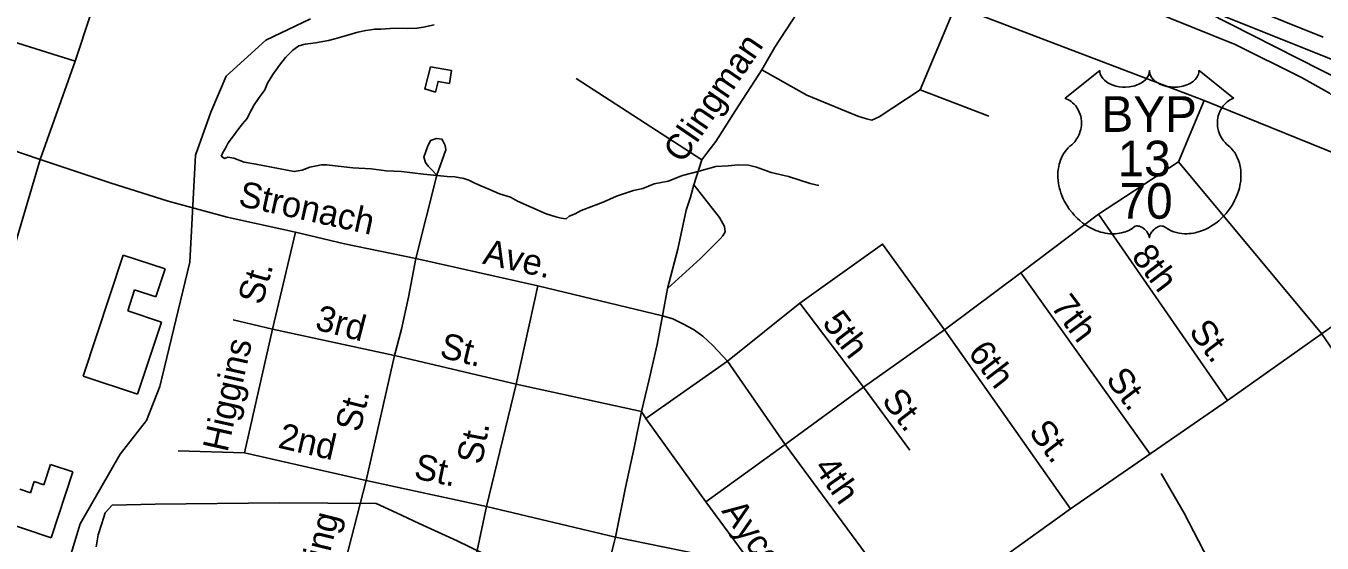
# Model space of a CAD drawing. Extents: x 2260773 to 2342389, y 552869 to 618546.
# Drawn here: x 2301642 to 2306454, y 599328 to 601248 of the extents above; entities that cross this region are included whole.
import ezdxf

# ---------------------------------------------------------------- set-up
doc = ezdxf.new("R2010")
doc.units = 0
for name, color, linetype in [('Exist Cultural Warehouse Building Footprint', 7, 'Continuous'), ('Exist Hydrographic Misc Water Feature', 7, 'Continuous'), ('Exist Road Non-System Type 51', 7, 'Continuous'), ('Exist Road Non-System Type 51 Label', 7, 'Continuous'), ('Exist Road Primary Interstate Ramp 1 Lane Attributed', 7, 'Continuous'), ('Exist Road Primary US Divided Attributed', 7, 'Continuous'), ('Exist Road Primary US Service Attributed', 7, 'Continuous'), ('Exist Road Primary US Shield CELL', 7, 'Continuous'), ('Exist Road Primary US Shield Number Label', 7, 'Continuous'), ('Exist Road Primary US UnDivided 4 Lane Attributed', 7, 'Continuous'), ('Exist Road Secondary Type 51 Undivided 4 Lane Attributed', 7, 'Continuous')]:
    doc.layers.add(name, color=color, linetype=linetype)

msp = doc.modelspace()

# ---------------------------------------------------------------- linework, layer by layer
at = {"layer": 'Exist Cultural Warehouse Building Footprint'}
for p, q in [((2302003.2, 600397.2), (2301854.2, 599947.3)), ((2302158.7, 600345.7), (2302003.2, 600397.2)), ((2302124.4, 600241.9), (2302158.7, 600345.7)), ((2302019.7, 600189.9), (2302045.5, 600268)), ((2302045.5, 600268), (2302124.4, 600241.9)), ((2302145.1, 600148.4), (2302019.7, 600189.9)), ((2302056.4, 599880.4), (2302145.1, 600148.4)), ((2301854.2, 599947.3), (2302056.4, 599880.4)), ((2301708.1, 599544.3), (2301733.2, 599619.6)), ((2301733.2, 599619.6), (2301816.7, 599591.8)), ((2301816.7, 599591.8), (2301735.4, 599347.4)), ((2301658.7, 599514.7), (2301672.5, 599556.1)), ((2301672.5, 599556.1), (2301708.1, 599544.3)), ((2301619.8, 599527.7), (2301658.7, 599514.7)), ((2301735.4, 599347.4), (2301497.8, 599426.6))]:
    msp.add_line(p, q, dxfattribs=at)
at = {"layer": 'Exist Hydrographic Misc Water Feature'}
for points in [[(2301559.9, 596453.9), (2301656.9, 596697.4), (2301736.1, 597048.4), (2301737.9, 597655.5), (2301785.1, 597906.8), (2301769.9, 598556), (2301742, 598889.5), (2301774, 598972.8), (2301772, 599163.1), (2301843.9, 599399), (2301992, 599657.6), (2302090, 599783), (2302139, 599909.7), (2302249.9, 600370.4), (2302271.1, 600768.2), (2302328.1, 600928), (2302385.1, 601061.6), (2302532.9, 601195.6), (2302699, 601274.5)], [(2303157.9, 601252.1), (2303117.9, 601244), (2303093.7, 601239.5), (2303058.1, 601239.2), (2303016.2, 601240.6), (2302994.1, 601238.7), (2302960, 601236.1), (2302935.8, 601236.1), (2302922.3, 601233.7), (2302904.1, 601231.6), (2302874.1, 601225.1), (2302832.5, 601212.7), (2302788.4, 601200.3), (2302764.8, 601194.2), (2302716.6, 601185.5), (2302698.8, 601183.4), (2302678.5, 601181.2), (2302654.9, 601175), (2302633.2, 601158.8), (2302605.5, 601130.5), (2302583.8, 601102.2), (2302558.1, 601067.9), (2302538.3, 601035.6), (2302528.8, 601011.5), (2302505.2, 600979.4), (2302489.7, 600955.3), (2302472, 600923.1), (2302463.8, 600904.9), (2302446, 600884.8), (2302428.3, 600862.8), (2302412.8, 600840.4), (2302393.1, 600814.1), (2302381.4, 600792), (2302373, 600778.3), (2302369.7, 600768.2), (2302367.2, 600764.1)], [(2303143.4, 601096.2), (2303221.5, 601083.2), (2303213.9, 601034.9), (2303171.9, 601042.4), (2303162.2, 601002.5), (2303122.4, 601014.2), (2303143.4, 601096.2)], [(2304585.3, 600656), (2304553.5, 600663.6), (2304473.1, 600688.7), (2304408.9, 600704.1), (2304354.8, 600723.6), (2304324.9, 600730.9), (2304286.5, 600732.6), (2304248.8, 600728.2), (2304202.9, 600725.8), (2304141.1, 600709.1), (2304079.2, 600692.5), (2304025.7, 600671.7), (2303973.8, 600661.3), (2303932, 600644.9), (2303897.7, 600636.7), (2303872.1, 600628.4), (2303834, 600615.9), (2303784.4, 600593.3), (2303748.7, 600580.8), (2303703.2, 600562.5), (2303681.2, 600550.4), (2303659.3, 600542), (2303647.6, 600532), (2303629.5, 600533.9), (2303609.2, 600539.4), (2303572.9, 600551), (2303466.7, 600598.1), (2303440.7, 600611.8), (2303400.3, 600625.2), (2303360.3, 600642.6), (2303330.4, 600654.4), (2303306, 600666.1), (2303286.1, 600676), (2303267.8, 600681.6), (2303234, 600687.6), (2303205.7, 600689), (2303117.5, 600698.2), (2303035.7, 600707.3), (2302979.7, 600710.8), (2302923.5, 600718.1), (2302855.7, 600721.4), (2302789.8, 600728.5), (2302759.3, 600732.2), (2302739.8, 600732), (2302695.9, 600723.6), (2302667.8, 600713.2), (2302637.9, 600707.2), (2302612.1, 600712.6), (2302554, 600724.2), (2302496, 600735.4), (2302451.7, 600742.9), (2302413.8, 600756.7), (2302391.4, 600760.5), (2302379.5, 600756.2), (2302367.2, 600764.1)], [(2305856.6, 599586.2), (2305941.7, 599439.2), (2306031.5, 599266.3), (2305926.9, 599163.2), (2305800, 599042)], [(2301961.6, 599468.3), (2301936.2, 599440.1), (2301924.3, 599400), (2301910.6, 599358), (2301903.2, 599314)], [(2303383.1, 599268), (2303242.4, 599336.3), (2303101.7, 599400.8), (2303017.5, 599439.9), (2302942.8, 599475), (2302583.2, 599476.9), (2302121.8, 599472.2), (2301961.6, 599468.3)]]:
    msp.add_lwpolyline(points, dxfattribs=at)
at = {"layer": 'Exist Road Non-System Type 51'}
for p, q in [((2305093.3, 601322.4), (2304962.3, 601010.4)), ((2306016.8, 600971.8), (2305093.3, 601322.4)), ((2301549.4, 601204.5), (2301824.6, 601116.9)), ((2304151.8, 600751.4), (2303684.3, 601053.7)), ((2304962.3, 601010.4), (2305217.3, 600912.8)), ((2305920.8, 600743.5), (2306016.8, 600971.8)), ((2306016.8, 600971.8), (2306596, 600735.6)), ((2301354.4, 600866.2), (2301691.7, 600753.2)), ((2301691.7, 600753.2), (2301694.9, 600752.1)), ((2304151.8, 600751.4), (2304121.9, 600658.4)), ((2305623.4, 600549.8), (2305920.8, 600743.5)), ((2306451.7, 600105.6), (2305920.8, 600743.5)), ((2303089.4, 600384.4), (2303167.6, 600693.8)), ((2305335.3, 600330.9), (2305623.4, 600549.8)), ((2305623.4, 600549.8), (2306103.4, 599857.6)), ((2302642.4, 600482.1), (2302557.4, 600122.2)), ((2303542.7, 600283.2), (2303089.4, 600384.4)), ((2305052, 600119.8), (2305335.3, 600330.9)), ((2305335.3, 600330.9), (2305815.4, 599658.4)), ((2303462.4, 599917.8), (2303542.7, 600283.2)), ((2304005.4, 600171.4), (2303542.7, 600283.2)), ((2304005.4, 600171.4), (2304023.8, 600273.3)), ((2304515.3, 600219), (2304246.2, 600003.3)), ((2304751.4, 599907.2), (2304515.3, 600219)), ((2302557.4, 600122.2), (2302411, 600156.8)), ((2302557.4, 600122.2), (2302453.5, 599662.3)), ((2303010.7, 600023.8), (2302557.4, 600122.2)), ((2305052, 600119.8), (2304751.4, 599907.2)), ((2305519.5, 599454.4), (2305052, 600119.8)), ((2306657.9, 599804.5), (2306451.7, 600105.6)), ((2302905.2, 599560), (2303010.7, 600023.8)), ((2303462.4, 599917.8), (2303010.7, 600023.8)), ((2303943.6, 599790.4), (2304246.2, 600003.3)), ((2304246.2, 600003.3), (2304460.2, 599693.4)), ((2303351.4, 599463.5), (2303462.4, 599917.8)), ((2303926.7, 599816.5), (2303462.4, 599917.8)), ((2304460.2, 599693.4), (2304751.4, 599907.2)), ((2304751.4, 599907.2), (2304923, 599672.6)), ((2303926.7, 599816.5), (2303943.6, 599790.4)), ((2303943.6, 599790.4), (2304165.9, 599480.8)), ((2304460.2, 599693.4), (2304165.9, 599480.8)), ((2304460.2, 599693.4), (2304943.4, 599040.2)), ((2302453.5, 599662.3), (2302207.2, 599670)), ((2302453.5, 599662.3), (2302905.2, 599560)), ((2302905.2, 599560), (2302719.8, 598839.3)), ((2302905.2, 599560), (2303351.4, 599463.5)), ((2303351.4, 599463.5), (2303277.1, 599111.2)), ((2303830.7, 599350.1), (2303351.4, 599463.5)), ((2304165.9, 599480.8), (2304339.1, 599246.2)), ((2303830.7, 599350.1), (2303743.3, 599002.8)), ((2303830.7, 599350.1), (2304315.5, 599251))]:
    msp.add_line(p, q, dxfattribs=at)
for points in [[(2304374.2, 601085.1), (2304421.9, 601169), (2304567.7, 601392.4), (2304681.1, 601608.7), (2304739.4, 601747.6)], [(2304374.2, 601085.1), (2304276.5, 600933.7), (2304203.8, 600818.9), (2304173.8, 600781.3), (2304151.8, 600751.4)], [(2304962.3, 601010.4), (2304809.6, 600911.2), (2304782.9, 600898.6), (2304762.4, 600903.3), (2304731, 600912.8), (2304540.5, 600991.5), (2304374.2, 601085.1)], [(2303167.6, 600693.8), (2303200.6, 600788.1), (2303198.5, 600804), (2303190.2, 600821.9), (2303186.2, 600827.9), (2303166.1, 600829.7), (2303144.3, 600823.4), (2303132.5, 600799.4), (2303118.9, 600761.2), (2303125.3, 600741.2), (2303135.2, 600727.4), (2303147.5, 600715.5), (2303167.6, 600693.8)], [(2302642.4, 600482.1), (2302389, 600538.7), (2302170.2, 600597), (2301954.6, 600665.5), (2301694.9, 600752.1)], [(2304023.8, 600273.3), (2304146.5, 600384.5), (2304219.6, 600457.3), (2304229.5, 600469.3), (2304237.4, 600483.4), (2304235.2, 600503.3), (2304216.8, 600537.2), (2304121.9, 600658.4)], [(2304121.9, 600658.4), (2304109.3, 600612.8), (2304093.5, 600563.9), (2304062, 600419.1), (2304023.8, 600273.3)], [(2303089.4, 600384.4), (2302825, 600439.5), (2302642.4, 600482.1)], [(2304515.3, 600219), (2304822.2, 600438), (2305052, 600119.8)], [(2303010.7, 600023.8), (2303035.9, 600122.7), (2303062.5, 600241), (2303089.4, 600384.4)], [(2304005.4, 600171.4), (2303986, 600064.9), (2303955, 599930.4), (2303926.7, 599816.5)], [(2304005.4, 600171.4), (2304043.2, 600160.8), (2304080.9, 600141.9), (2304120.3, 600121.4), (2304154.9, 600096.2), (2304192.7, 600061.6), (2304246.2, 600003.3)], [(2303926.7, 599816.5), (2303901.5, 599687.1), (2303868.5, 599534.4), (2303830.7, 599350.1)]]:
    msp.add_lwpolyline(points, dxfattribs=at)
at = {"layer": 'Exist Road Primary Interstate Ramp 1 Lane Attributed'}
msp.add_lwpolyline([(2305943.3, 601341.9), (2306533.5, 601042), (2306661.7, 600978.3), (2306830.2, 600877.6), (2306989.1, 600749.3), (2307091.9, 600635.8), (2307128, 600582.8)], dxfattribs=at)
at = {"layer": 'Exist Road Primary US Divided Attributed'}
for points in [[(2306457.9, 601206.3), (2305432, 601620.2), (2304253, 602092.7), (2304041, 602171.5), (2303732.6, 602271.1), (2303680.3, 602281)], [(2305943.3, 601341.9), (2305984.3, 601326.3), (2307418.8, 600752.8)]]:
    msp.add_lwpolyline(points, dxfattribs=at)
at = {"layer": 'Exist Road Primary US Service Attributed'}
msp.add_lwpolyline([(2306887.2, 600412.8), (2306747.5, 600679.3), (2306680.8, 600793.8), (2306629.1, 600867.9), (2306481.5, 600998.5), (2306377.7, 601056.8), (2306131.8, 601179.8), (2304126.9, 601988.9), (2303905.9, 602071.4), (2303809, 602103.4), (2303599.2, 602158.5), (2303401, 602197.7), (2303254.8, 602203.1), (2303190.1, 602190.3), (2302912.5, 602066.8), (2302872.2, 602053), (2302841.5, 602052), (2302810.8, 602061.5), (2302785.3, 602079.5), (2302761, 602109.2)], dxfattribs=at)
at = {"layer": 'Exist Road Primary US Shield CELL'}
msp.add_lwpolyline([(2305629, 601082.2), (2305629.4, 601076.9), (2305630.7, 601070.6), (2305631.6, 601067.3), (2305634.6, 601061.1), (2305639.5, 601053.7), (2305646.3, 601046.5), (2305653.9, 601040.2), (2305659.1, 601036.8), (2305667.9, 601032.1), (2305677.8, 601027.9), (2305688.9, 601024.8), (2305700.2, 601022.5), (2305712.6, 601021.1), (2305724.8, 601020.9), (2305738, 601021.9), (2305752.6, 601024.7), (2305759.4, 601026.4), (2305766.9, 601029), (2305773.9, 601031.9), (2305781.6, 601036), (2305787.7, 601040), (2305792.5, 601043.5), (2305799.4, 601050), (2305804.8, 601056.7), (2305807.1, 601060.5), (2305809.1, 601064.2), (2305811.7, 601071.9), (2305812.5, 601075.4), (2305813, 601082.5), (2305813.5, 601076.5), (2305814.1, 601072.8), (2305815.1, 601069.1), (2305816.6, 601065.3), (2305819.3, 601059.8), (2305822.4, 601055.2), (2305828.1, 601048.5), (2305831.7, 601045.1), (2305835, 601042.5), (2305843.7, 601036.5), (2305853.9, 601031.3), (2305858.9, 601029.1), (2305864.1, 601027.3), (2305870.6, 601025.3), (2305877.4, 601023.7), (2305884.1, 601022.6), (2305890.9, 601021.6), (2305897.9, 601021), (2305903.6, 601020.9), (2305910.6, 601021), (2305917, 601021.3), (2305923.6, 601022.1), (2305930.9, 601023.3), (2305936.8, 601024.6), (2305944.5, 601026.7), (2305951.5, 601029.2), (2305957.6, 601031.8), (2305965.6, 601036), (2305972.1, 601040), (2305976.8, 601043.8), (2305982.4, 601049), (2305987.7, 601055.2), (2305990.8, 601059.6), (2305993, 601064.3), (2305995.1, 601069.1), (2305996.3, 601074.3), (2305997, 601078.8), (2305997.1, 601082.6), (2306125.7, 600980.2), (2306122.6, 600979), (2306115.7, 600975.6), (2306110.1, 600972.3), (2306101.3, 600966.1), (2306097.5, 600962.7), (2306093.7, 600959.1), (2306090.2, 600955.3), (2306087.1, 600951.7), (2306083.4, 600946.6), (2306080, 600941.4), (2306076.8, 600935.7), (2306074.4, 600930.8), (2306070.4, 600920.4), (2306068.5, 600913.9), (2306067.3, 600908.3), (2306065.8, 600896.9), (2306065.4, 600891.4), (2306065.4, 600886), (2306065.7, 600880.3), (2306066.2, 600874.8), (2306067.2, 600869.1), (2306068.1, 600864.1), (2306069.7, 600858), (2306072, 600850.8), (2306074.8, 600843.9), (2306080.7, 600832.7), (2306088.3, 600821.3), (2306093.7, 600815), (2306099, 600809.5), (2306106.9, 600802.8), (2306111.2, 600799), (2306116.1, 600794.1), (2306124.2, 600784.7), (2306127.5, 600780.3), (2306130.8, 600775.4), (2306133.8, 600770.3), (2306136.8, 600764.8), (2306139.3, 600760), (2306143.8, 600749), (2306147.1, 600738.3), (2306148.6, 600732.7), (2306151, 600720), (2306151.9, 600713.8), (2306152.9, 600701.5), (2306152.9, 600686.6), (2306151.8, 600672.5), (2306149.1, 600656), (2306146.9, 600646.1), (2306143.6, 600634.6), (2306140.3, 600624.7), (2306134.4, 600610), (2306129.2, 600599.4), (2306122.5, 600586.9), (2306117.8, 600579.4), (2306112.4, 600571.3), (2306105.7, 600562.1), (2306097.8, 600552.2), (2306088.3, 600541.8), (2306080.6, 600534.1), (2306070.6, 600525.1), (2306064.5, 600520.1), (2306055.8, 600513.6), (2306044, 600505.7), (2306032.3, 600498.9), (2306022.4, 600493.8), (2306013.5, 600490), (2306002.2, 600485.7), (2305983.2, 600480.5), (2305976.3, 600479), (2305968.1, 600477.8), (2305960.4, 600477), (2305952.9, 600476.6), (2305942.9, 600476.6), (2305933, 600477.3), (2305923.5, 600478.7), (2305913.7, 600480.8), (2305903.5, 600483.8), (2305894.2, 600487.5), (2305884.8, 600492.1), (2305868.9, 600502.1), (2305864.3, 600504.5), (2305861.7, 600505.2), (2305855.5, 600505.5), (2305849.8, 600504.3), (2305843.8, 600502), (2305840.3, 600500.1), (2305835.5, 600496.9), (2305831.9, 600494.1), (2305827.5, 600489.9), (2305824.4, 600486.4), (2305822.1, 600483.7), (2305817.6, 600476.6), (2305816, 600473.2), (2305814.4, 600468.9), (2305812.9, 600462.5), (2305810.9, 600470.6), (2305808.5, 600475.9), (2305805.8, 600480.5), (2305802.9, 600484.5), (2305798.5, 600489.7), (2305794.4, 600493.5), (2305789.6, 600497.5), (2305784.4, 600500.6), (2305780.3, 600502.7), (2305776.5, 600504.2), (2305771.8, 600505.3), (2305768, 600505.6), (2305764.9, 600505.5), (2305760.6, 600504.6), (2305754.8, 600500.4), (2305749.3, 600496.6), (2305743.3, 600492.8), (2305736.2, 600489), (2305730.9, 600486.6), (2305724.7, 600484.2), (2305717.4, 600481.8), (2305709.5, 600479.7), (2305701.4, 600478.1), (2305694.3, 600477), (2305686.6, 600476.3), (2305679.7, 600476.1), (2305672.5, 600476.1), (2305665.7, 600476.7), (2305657.9, 600477.3), (2305648.2, 600478.8), (2305640.1, 600480.6), (2305631.6, 600482.9), (2305622.9, 600485.6), (2305613.5, 600489.2), (2305601.8, 600494.3), (2305593.7, 600498.5), (2305580.9, 600505.8), (2305565.8, 600516.3), (2305554.5, 600525.4), (2305546.2, 600533), (2305533.9, 600545.4), (2305526.8, 600553.6), (2305515.5, 600568.1), (2305508.3, 600578.7), (2305503.6, 600586.5), (2305496.8, 600598.9), (2305493, 600606.7), (2305488.1, 600618.1), (2305484.3, 600628.6), (2305481.1, 600638.4), (2305479.4, 600644.7), (2305477, 600655.8), (2305475.5, 600663.6), (2305474.1, 600674.3), (2305473.3, 600685.6), (2305473.1, 600696), (2305473.4, 600704.7), (2305474.4, 600714.8), (2305476.1, 600725.5), (2305478.1, 600734.7), (2305480, 600741.3), (2305482.7, 600749.4), (2305486.3, 600758.3), (2305490.6, 600766.8), (2305494.6, 600773.8), (2305499.7, 600781.4), (2305504.7, 600787.9), (2305511.3, 600795), (2305518.1, 600801.6), (2305524.4, 600806.7), (2305531.9, 600814), (2305535.7, 600818.4), (2305540.4, 600824.5), (2305544.1, 600830.2), (2305547.1, 600835.3), (2305551, 600842.8), (2305553.3, 600848.5), (2305556.3, 600857.1), (2305557.8, 600863.2), (2305559.3, 600871), (2305560.3, 600878.4), (2305560.7, 600887.6), (2305560.4, 600895.2), (2305559.5, 600904.1), (2305557.8, 600912.6), (2305555.8, 600920), (2305552.6, 600928.6), (2305549.7, 600934.8), (2305544.7, 600943.2), (2305539.3, 600951), (2305533.6, 600957.4), (2305527.9, 600963.1), (2305522.4, 600967.4), (2305517.2, 600971.1), (2305510.7, 600975.1), (2305504.4, 600978.2), (2305500.4, 600979.8)], close=True, dxfattribs=at)
at = {"layer": 'Exist Road Primary US UnDivided 4 Lane Attributed'}
msp.add_lwpolyline([(2301176, 599183.7), (2301348.9, 599697.6), (2301474.6, 600047.9), (2301592.3, 600404.5), (2301694.9, 600752.1), (2301824.6, 601116.9), (2301939.5, 601466.2), (2302012.9, 601683.1), (2302022.4, 601711.8), (2302103, 601952.7), (2302152.4, 602118.3), (2302179.9, 602208.4)], dxfattribs=at)
at = {"layer": 'Exist Road Secondary Type 51 Undivided 4 Lane Attributed'}
msp.add_lwpolyline([(2306887.2, 600412.8), (2306103.4, 599857.6), (2305519.5, 599454.4), (2304943.4, 599040.2), (2304849, 598957.9), (2304668, 598783.1), (2304578.3, 598687.9), (2304346.9, 598464.1)], dxfattribs=at)

# ---------------------------------------------------------------- texts
at = {"layer": 'Exist Road Non-System Type 51 Label'}
for s, rotation, p in [('Clingman', 55.6302, (2304080.3, 600734)), ('Stronach', 347.6179, (2302426.9, 600581.2)), ('Ave.', 347.3656, (2303334, 600366.1)), ('8th', 307.3674, (2305742.9, 600392.1)), ('St.', 73.9147, (2302518.1, 600208.6)), ('7th', 307.0497, (2305443.6, 600205.9)), ('3rd', 345.5822, (2302711.4, 600121.9)), ('5th', 307.4352, (2304595.1, 600145)), ('St.', 307.3674, (2305956, 600113)), ('Higgins', 77.4258, (2302390, 599662.2)), ('St.', 346.0892, (2303173.7, 600018.9)), ('6th', 307.5544, (2305136.1, 600033.5)), ('St.', 307.0497, (2305647.9, 599935.2)), ('St.', 76.097, (2302881.3, 599736)), ('St.', 307.603, (2304815.9, 599856.8)), ('St.', 307.5544, (2305361.6, 599740.2)), ('2nd', 346.9938, (2302574.1, 599682.8)), ('St.', 79.0078, (2303334, 599616.5)), ('St.', 348.2373, (2303078.8, 599568.7)), ('4th', 305.2101, (2304564.3, 599607.7)), ('Herring', 76.1167, (2302705.6, 599025.1)), ('Aycock', 305.4624, (2304222.3, 599446.5))]:
    msp.add_text(s, height=95, rotation=rotation, dxfattribs=at).set_placement(p)
at = {"layer": 'Exist Road Primary US Shield Number Label'}
for s, p in [('BYP', (2305634.9, 600854.8)), ('13', (2305694.8, 600689.7)), ('70', (2305702.3, 600532.3))]:
    msp.add_text(s, height=132.5, dxfattribs=at).set_placement(p)

doc.saveas('drawing.dxf')
